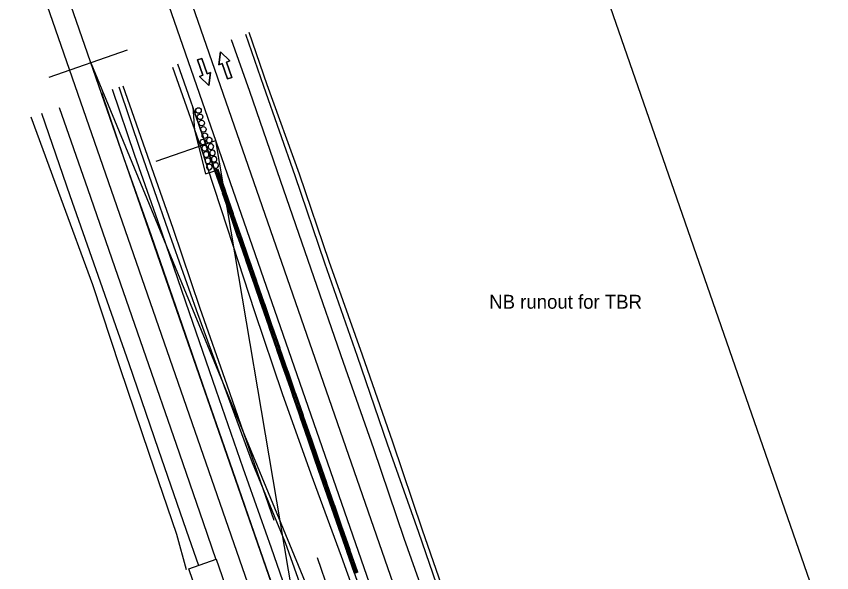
# Model space of a CAD drawing. Extents: x 16415773 to 16419292, y 7112293 to 7123690.
# Drawn here: x 16416960.7 to 16417401, y 7118425.7 to 7118726 of the extents above; entities that cross this region are included whole.
import ezdxf

# ---------------------------------------------------------------- set-up
doc = ezdxf.new("R2010")
doc.units = 0
for name, color, linetype in [('Bridge', 7, 'Continuous'), ('Drainage', 7, 'Continuous'), ('EXT_BNK', 7, 'Continuous'), ('EXT_CU', 7, 'Continuous'), ('EXT_GU', 7, 'Continuous'), ('NamedBoundary', 7, 'Continuous'), ('PavementMarking', 7, 'Continuous'), ('Roadways', 7, 'Continuous'), ('Stage_3_Pvt_Mk_Removal', 7, 'Continuous'), ('SurNaturalCells', 7, 'Continuous'), ('SurPointsNonDTM', 7, 'Continuous'), ('SurSurveyPoints', 7, 'Continuous'), ('TBR_Path', 7, 'Continuous'), ('Text', 7, 'Continuous')]:
    doc.layers.add(name, color=color, linetype=linetype)

msp = doc.modelspace()

# ---------------------------------------------------------------- linework, layer by layer
at = {"layer": 'Bridge'}
for points in [[(16417218.7, 7118305.24), (16417204.44, 7118346.2), (16417188.08, 7118393.92), (16417170.23, 7118444.21), (16417153.76, 7118492.49), (16417137.48, 7118539.23), (16417119.91, 7118589.53), (16417103.4, 7118637.47), (16417086.86, 7118685.52), (16417076.94, 7118713.35)], [(16417112.01, 7118381.83), (16417106.85, 7118396.66), (16417092.64, 7118437.51), (16417077.57, 7118480.7), (16417063.29, 7118522.07), (16417048.68, 7118564.39), (16417033.75, 7118607.45), (16417018.84, 7118649.55), (16417006.84, 7118684.74)], [(16416983.83, 7118676.8), (16416999.28, 7118632.58), (16417015.37, 7118586.36), (16417030.75, 7118542.17), (16417047.14, 7118495.07), (16417061.64, 7118452.69), (16417068.47, 7118432.88)]]:
    msp.add_lwpolyline(points, dxfattribs=at)
at = {"layer": 'Drainage'}
for p, q in [((16417099.92, 7118453.81), (16417083.52, 7118501.04)), ((16417193.95, 7118230.57), (16417123.41, 7118433.67))]:
    msp.add_line(p, q, dxfattribs=at)
at = {"layer": 'EXT_BNK'}
msp.add_lwpolyline([(16417053.87, 7118427.81), (16417068.62, 7118432.93), (16417124.35, 7118272.47), (16417111.49, 7118268.01), (16417078.73, 7118362.34), (16417060.43, 7118408.91)], close=True, dxfattribs=at)
at = {"layer": 'EXT_CU'}
for points in [[(16417228.72, 7118308.72), (16417214.34, 7118350.22), (16417197.7, 7118397.97), (16417180.05, 7118448.61), (16417164.02, 7118496.17), (16417147.61, 7118543.12), (16417129.67, 7118593.7), (16417113.57, 7118640.8), (16417096.22, 7118689.13), (16417086.48, 7118717.28)], [(16417045.08, 7118698.62), (16417060.17, 7118655.72), (16417074.57, 7118611.88), (16417089.36, 7118566.69), (16417104.35, 7118522.34), (16417119.86, 7118479.01), (16417136.1, 7118434.61), (16417151.37, 7118391.89), (16417165, 7118351.61), (16417181.01, 7118306.54), (16417185.64, 7118293.76)], [(16417128.66, 7118387.61), (16417122.39, 7118403.4), (16417119.78, 7118403.24), (16417106.07, 7118441.72), (16417088.35, 7118484.96), (16417072.91, 7118526.64), (16417058.05, 7118567.41), (16417042.77, 7118610.65), (16417028.04, 7118653.06), (16417016.23, 7118687.83)], [(16416968.57, 7118671.83), (16416984.69, 7118627.65), (16417001.83, 7118581.34), (16417016.61, 7118536.41), (16417032.31, 7118490.29), (16417047.28, 7118446.46), (16417052.53, 7118427.34)]]:
    msp.add_lwpolyline(points, dxfattribs=at)
at = {"layer": 'EXT_GU'}
msp.add_lwpolyline([(16417083.52, 7118501.04), (16417074.51, 7118526.85), (16417060.08, 7118568.28), (16417045.35, 7118611.44), (16417030.51, 7118653.91), (16417018.41, 7118688.41)], dxfattribs=at)
at = {"layer": 'NamedBoundary'}
msp.add_lwpolyline([(16417248.82, 7117301.47), (16417721.14, 7117465.51), (16417206.86, 7118946.25), (16416734.54, 7118782.2)], close=True, dxfattribs=at)
at = {"layer": 'PavementMarking'}
for p, q in [((16417969.62, 7116100.87), (16416631.03, 7119955.58)), ((16417958.29, 7116096.93), (16416619.69, 7119951.64)), ((16417958.29, 7116096.93), (16416619.69, 7119951.64))]:
    msp.add_line(p, q, dxfattribs=at)
at = {"layer": 'Roadways'}
for points in [[(16417226.51, 7118307.96), (16417212.32, 7118349.1), (16417195.45, 7118397.16), (16417178.04, 7118447.44), (16417161.26, 7118495.11), (16417145.01, 7118542.39), (16417127.31, 7118592.71), (16417111.36, 7118639.91), (16417094.46, 7118688.1), (16417084.59, 7118716.3)], [(16417047.83, 7118700.4), (16417063.02, 7118656.76), (16417078.14, 7118613.29), (16417093.27, 7118569.53), (16417108.72, 7118524.75), (16417123.75, 7118481.11), (16417139.45, 7118436.4), (16417154.5, 7118393.55), (16417168.4, 7118353.07), (16417183.92, 7118308.51), (16417188.67, 7118294.81)], [(16417126.52, 7118386.87), (16417121.48, 7118402.18), (16417112.43, 7118399.03), (16417098.46, 7118438.85), (16417083.32, 7118482.09), (16417068.74, 7118524.21), (16417054.3, 7118565.95), (16417039.41, 7118608.93), (16417024.74, 7118650.98), (16417012.63, 7118686.61)], [(16416974.29, 7118673.72), (16416989.64, 7118629.26), (16417005.97, 7118582.68), (16417021.43, 7118538.68), (16417037.34, 7118492.38), (16417052.4, 7118448.56), (16417059.03, 7118429.6)]]:
    msp.add_lwpolyline(points, dxfattribs=at)
at = {"layer": 'Stage_3_Pvt_Mk_Removal'}
for p, q in [((16417965.92, 7115922.49), (16416627.37, 7119776.57)), ((16417954.59, 7115918.56), (16416616.03, 7119772.63))]:
    msp.add_line(p, q, dxfattribs=at)
at = {"layer": 'SurNaturalCells'}
for p, q in [((16417069.69, 7118643.3), (16417067.92, 7118642.69)), ((16417072.02, 7118630.88), (16417067.92, 7118642.69)), ((16417072.59, 7118631.08), (16417068.49, 7118642.89)), ((16417073.22, 7118631.3), (16417069.13, 7118643.11)), ((16417073.79, 7118631.5), (16417069.69, 7118643.3)), ((16417073.79, 7118631.5), (16417072.02, 7118630.88)), ((16417073.89, 7118631.21), (16417072.12, 7118630.6)), ((16417076.22, 7118618.79), (16417072.12, 7118630.6)), ((16417076.78, 7118618.98), (16417072.68, 7118630.79)), ((16417077.42, 7118619.2), (16417073.32, 7118631.01)), ((16417077.99, 7118619.4), (16417073.89, 7118631.21)), ((16417077.99, 7118619.4), (16417076.22, 7118618.79)), ((16417078.09, 7118619.12), (16417076.32, 7118618.5)), ((16417080.41, 7118606.69), (16417076.32, 7118618.5)), ((16417080.98, 7118606.89), (16417076.88, 7118618.7)), ((16417081.62, 7118607.11), (16417077.52, 7118618.92)), ((16417082.18, 7118607.31), (16417078.09, 7118619.12)), ((16417082.18, 7118607.31), (16417080.41, 7118606.69)), ((16417082.28, 7118607.02), (16417080.51, 7118606.41)), ((16417085.81, 7118595.02), (16417081.72, 7118606.82)), ((16417086.38, 7118595.21), (16417082.28, 7118607.02)), ((16417084.61, 7118594.6), (16417080.51, 7118606.41)), ((16417085.18, 7118594.79), (16417081.08, 7118606.6)), ((16417086.38, 7118595.21), (16417084.61, 7118594.6)), ((16417086.48, 7118594.93), (16417084.71, 7118594.31)), ((16417088.81, 7118582.5), (16417084.71, 7118594.31)), ((16417089.37, 7118582.7), (16417085.28, 7118594.51)), ((16417090.01, 7118582.92), (16417085.91, 7118594.73)), ((16417090.58, 7118583.12), (16417086.48, 7118594.93)), ((16417090.58, 7118583.12), (16417088.81, 7118582.5)), ((16417090.68, 7118582.83), (16417088.91, 7118582.22)), ((16417093, 7118570.41), (16417088.91, 7118582.22)), ((16417093.57, 7118570.6), (16417089.47, 7118582.41)), ((16417094.21, 7118570.83), (16417090.11, 7118582.64)), ((16417094.78, 7118571.02), (16417090.68, 7118582.83)), ((16417094.78, 7118571.02), (16417093, 7118570.41)), ((16417094.87, 7118570.74), (16417093.1, 7118570.12)), ((16417097.2, 7118558.31), (16417093.1, 7118570.12)), ((16417097.77, 7118558.51), (16417093.67, 7118570.32)), ((16417098.41, 7118558.73), (16417094.31, 7118570.54)), ((16417098.97, 7118558.93), (16417094.87, 7118570.74)), ((16417098.97, 7118558.93), (16417097.2, 7118558.31)), ((16417099.07, 7118558.64), (16417097.3, 7118558.03)), ((16417102.6, 7118546.64), (16417098.51, 7118558.45)), ((16417103.17, 7118546.83), (16417099.07, 7118558.64)), ((16417101.4, 7118546.22), (16417097.3, 7118558.03)), ((16417101.97, 7118546.42), (16417097.87, 7118558.22)), ((16417103.17, 7118546.83), (16417101.4, 7118546.22)), ((16417103.27, 7118546.55), (16417101.5, 7118545.93)), ((16417105.6, 7118534.12), (16417101.5, 7118545.93)), ((16417106.16, 7118534.32), (16417102.06, 7118546.13)), ((16417106.8, 7118534.54), (16417102.7, 7118546.35)), ((16417107.37, 7118534.74), (16417103.27, 7118546.55)), ((16417107.37, 7118534.74), (16417105.6, 7118534.12)), ((16417107.47, 7118534.45), (16417105.69, 7118533.84)), ((16417109.79, 7118522.03), (16417105.69, 7118533.84)), ((16417110.36, 7118522.23), (16417106.26, 7118534.04)), ((16417111, 7118522.45), (16417106.9, 7118534.26)), ((16417111.56, 7118522.64), (16417107.47, 7118534.45)), ((16417111.56, 7118522.64), (16417109.79, 7118522.03)), ((16417111.66, 7118522.36), (16417109.89, 7118521.74)), ((16417113.99, 7118509.93), (16417109.89, 7118521.74)), ((16417114.56, 7118510.13), (16417110.46, 7118521.94)), ((16417115.19, 7118510.35), (16417111.1, 7118522.16)), ((16417115.76, 7118510.55), (16417111.66, 7118522.36)), ((16417115.76, 7118510.55), (16417113.99, 7118509.93)), ((16417115.86, 7118510.26), (16417114.09, 7118509.65)), ((16417119.39, 7118498.26), (16417115.29, 7118510.07)), ((16417119.96, 7118498.46), (16417115.86, 7118510.26)), ((16417118.19, 7118497.84), (16417114.09, 7118509.65)), ((16417118.75, 7118498.04), (16417114.66, 7118509.85)), ((16417119.96, 7118498.46), (16417118.19, 7118497.84)), ((16417120.06, 7118498.17), (16417118.29, 7118497.55)), ((16417122.38, 7118485.75), (16417118.29, 7118497.55)), ((16417122.95, 7118485.94), (16417118.85, 7118497.75)), ((16417123.59, 7118486.16), (16417119.49, 7118497.97)), ((16417124.16, 7118486.36), (16417120.06, 7118498.17)), ((16417124.16, 7118486.36), (16417122.38, 7118485.75)), ((16417124.25, 7118486.08), (16417122.48, 7118485.46)), ((16417126.58, 7118473.65), (16417122.48, 7118485.46)), ((16417127.15, 7118473.85), (16417123.05, 7118485.66)), ((16417127.79, 7118474.07), (16417123.69, 7118485.88)), ((16417128.35, 7118474.27), (16417124.25, 7118486.08)), ((16417128.35, 7118474.27), (16417126.58, 7118473.65)), ((16417128.45, 7118473.98), (16417126.68, 7118473.37)), ((16417130.78, 7118461.56), (16417126.68, 7118473.37)), ((16417131.35, 7118461.75), (16417127.25, 7118473.56)), ((16417131.98, 7118461.97), (16417127.88, 7118473.78)), ((16417132.55, 7118462.17), (16417128.45, 7118473.98)), ((16417132.55, 7118462.17), (16417130.78, 7118461.56)), ((16417132.65, 7118461.89), (16417130.88, 7118461.27)), ((16417135.54, 7118449.66), (16417131.44, 7118461.47)), ((16417136.18, 7118449.88), (16417132.08, 7118461.69)), ((16417136.75, 7118450.08), (16417132.65, 7118461.89)), ((16417134.98, 7118449.46), (16417130.88, 7118461.27)), ((16417136.75, 7118450.08), (16417134.98, 7118449.46)), ((16417136.85, 7118449.79), (16417135.07, 7118449.18)), ((16417139.17, 7118437.37), (16417135.07, 7118449.18)), ((16417139.74, 7118437.56), (16417135.64, 7118449.37)), ((16417140.38, 7118437.79), (16417136.28, 7118449.59)), ((16417140.94, 7118437.98), (16417136.85, 7118449.79)), ((16417140.94, 7118437.98), (16417139.17, 7118437.37)), ((16417141.04, 7118437.7), (16417139.27, 7118437.08)), ((16417143.37, 7118425.27), (16417139.27, 7118437.08)), ((16417143.94, 7118425.47), (16417139.84, 7118437.28)), ((16417144.57, 7118425.69), (16417140.48, 7118437.5)), ((16417145.14, 7118425.89), (16417141.04, 7118437.7)), ((16417145.14, 7118425.89), (16417143.37, 7118425.27))]:
    msp.add_line(p, q, dxfattribs=at)
for centre in [(16417068.76, 7118643.14), (16417072.95, 7118631.05), (16417072.95, 7118631.05), (16417077.15, 7118618.95), (16417077.15, 7118618.95), (16417081.35, 7118606.86), (16417081.35, 7118606.86), (16417085.55, 7118594.76), (16417085.55, 7118594.76), (16417089.74, 7118582.67), (16417089.74, 7118582.67), (16417093.94, 7118570.57), (16417093.94, 7118570.57), (16417098.14, 7118558.48), (16417098.14, 7118558.48), (16417102.33, 7118546.38), (16417102.33, 7118546.38), (16417106.53, 7118534.29), (16417106.53, 7118534.29), (16417110.73, 7118522.19), (16417110.73, 7118522.19), (16417114.93, 7118510.1), (16417114.93, 7118510.1), (16417119.12, 7118498), (16417119.12, 7118498), (16417123.32, 7118485.91), (16417123.32, 7118485.91), (16417127.52, 7118473.82), (16417127.52, 7118473.82), (16417131.71, 7118461.72), (16417131.71, 7118461.72), (16417135.91, 7118449.63), (16417135.91, 7118449.63), (16417140.11, 7118437.53), (16417140.11, 7118437.53)]:
    msp.add_circle(centre, 0.0521, dxfattribs=at)
for centre, start, end in [((16417068.81, 7118643), 19.138, 199.138), ((16417072.9, 7118631.19), 199.138, 19.138), ((16417073, 7118630.9), 19.138, 199.138), ((16417077.1, 7118619.09), 199.138, 19.138), ((16417077.2, 7118618.81), 19.138, 199.138), ((16417081.3, 7118607), 199.138, 19.138), ((16417081.4, 7118606.71), 19.138, 199.138), ((16417085.5, 7118594.9), 199.138, 19.138), ((16417085.6, 7118594.62), 19.138, 199.138), ((16417089.69, 7118582.81), 199.138, 19.138), ((16417089.79, 7118582.52), 19.138, 199.138), ((16417093.89, 7118570.72), 199.138, 19.138), ((16417093.99, 7118570.43), 19.138, 199.138), ((16417098.09, 7118558.62), 199.138, 19.138), ((16417098.19, 7118558.34), 19.138, 199.138), ((16417102.28, 7118546.53), 199.138, 19.138), ((16417102.38, 7118546.24), 19.138, 199.138), ((16417106.48, 7118534.43), 199.138, 19.138), ((16417106.58, 7118534.15), 19.138, 199.138), ((16417110.68, 7118522.34), 199.138, 19.138), ((16417110.78, 7118522.05), 19.138, 199.138), ((16417114.88, 7118510.24), 199.138, 19.138), ((16417114.97, 7118509.96), 19.138, 199.138), ((16417119.07, 7118498.15), 199.138, 19.138), ((16417119.17, 7118497.86), 19.138, 199.138), ((16417123.27, 7118486.05), 199.138, 19.138), ((16417123.37, 7118485.77), 19.138, 199.138), ((16417127.47, 7118473.96), 199.138, 19.138), ((16417127.57, 7118473.67), 19.138, 199.138), ((16417131.66, 7118461.86), 199.138, 19.138), ((16417131.76, 7118461.58), 19.138, 199.138), ((16417135.86, 7118449.77), 199.138, 19.138), ((16417135.96, 7118449.48), 19.138, 199.138), ((16417140.06, 7118437.67), 199.138, 19.138), ((16417140.16, 7118437.39), 19.138, 199.138)]:
    msp.add_arc(centre, 0.281, start, end, dxfattribs=at)
at = {"layer": 'SurPointsNonDTM'}
for p, q in [((16417067.92, 7118642.69), (16417056.02, 7118676.93)), ((16417056.02, 7118676.93), (16417056.89, 7118664.53)), ((16417056.89, 7118664.53), (16417062.95, 7118640.96)), ((16417062.95, 7118640.96), (16417067.92, 7118642.69))]:
    msp.add_line(p, q, dxfattribs=at)
at = {"layer": 'SurSurveyPoints'}
for centre in [(16417059.12, 7118675.19), (16417059.97, 7118671.79), (16417060.83, 7118668.4), (16417061.68, 7118665), (16417061.58, 7118658.24), (16417061.58, 7118658.24), (16417062.54, 7118661.61)]:
    msp.add_circle(centre, 1.5, dxfattribs=at)
for centre, start, end in [((16417064.97, 7118659.1), 99.1293, 279.1293), ((16417064.97, 7118659.1), 279.1293, 99.1293), ((16417062.43, 7118654.85), 99.1293, 279.1293), ((16417062.43, 7118654.85), 279.1293, 99.1293), ((16417065.83, 7118655.7), 99.1293, 279.1293), ((16417065.83, 7118655.7), 279.1293, 99.1293), ((16417063.29, 7118651.46), 99.1293, 279.1293), ((16417063.29, 7118651.46), 279.1293, 99.1293), ((16417066.68, 7118652.31), 99.1293, 279.1293), ((16417066.68, 7118652.31), 279.1293, 99.1293), ((16417064.14, 7118648.06), 99.1293, 279.1293), ((16417064.14, 7118648.06), 279.1293, 99.1293), ((16417067.54, 7118648.92), 99.1293, 279.1293), ((16417068.39, 7118645.52), 99.1293, 279.1293), ((16417067.54, 7118648.92), 279.1293, 99.1293), ((16417068.39, 7118645.52), 279.1293, 99.1293), ((16417065, 7118644.67), 99.1293, 279.1293), ((16417065, 7118644.67), 279.1293, 99.1293)]:
    msp.add_arc(centre, 1.5, start, end, dxfattribs=at)
at = {"layer": 'TBR_Path'}
for p, q in [((16417020.52, 7118707.72), (16416978.28, 7118693.05)), ((16417000.95, 7118700.92), (16417138.63, 7118367.64)), ((16417036.18, 7118647.79), (16417068.56, 7118659.03)), ((16417112.43, 7118399.03), (16417068.56, 7118659.03))]:
    msp.add_line(p, q, dxfattribs=at)
at = {"layer": 'Text'}
for points in [[(16417077.18, 7118693.08), (16417074.82, 7118692.26), (16417071.95, 7118700.52), (16417070.18, 7118699.91), (16417071.08, 7118706.84), (16417076.08, 7118701.96), (16417074.31, 7118701.34)], [(16417058.58, 7118702.49), (16417060.94, 7118703.31), (16417063.81, 7118695.05), (16417065.58, 7118695.66), (16417064.68, 7118688.73), (16417059.68, 7118693.61), (16417061.45, 7118694.23)]]:
    msp.add_lwpolyline(points, close=True, dxfattribs=at)
for points in [[(16417074.31, 7118701.34), (16417076.08, 7118701.96), (16417071.08, 7118706.84), (16417070.18, 7118699.91), (16417071.95, 7118700.52), (16417074.82, 7118692.26), (16417077.18, 7118693.08), (16417074.31, 7118701.34)], [(16417061.45, 7118694.23), (16417059.68, 7118693.61), (16417064.68, 7118688.73), (16417065.58, 7118695.66), (16417063.81, 7118695.05), (16417060.94, 7118703.31), (16417058.58, 7118702.49), (16417061.45, 7118694.23)]]:
    msp.add_lwpolyline(points, dxfattribs=at)

# ---------------------------------------------------------------- texts
at = {"layer": 'TBR_Path'}
msp.add_text('NB runout for TBR', height=7.5, dxfattribs=at).set_placement((16417216.11, 7118568.19))

doc.saveas('drawing.dxf')
